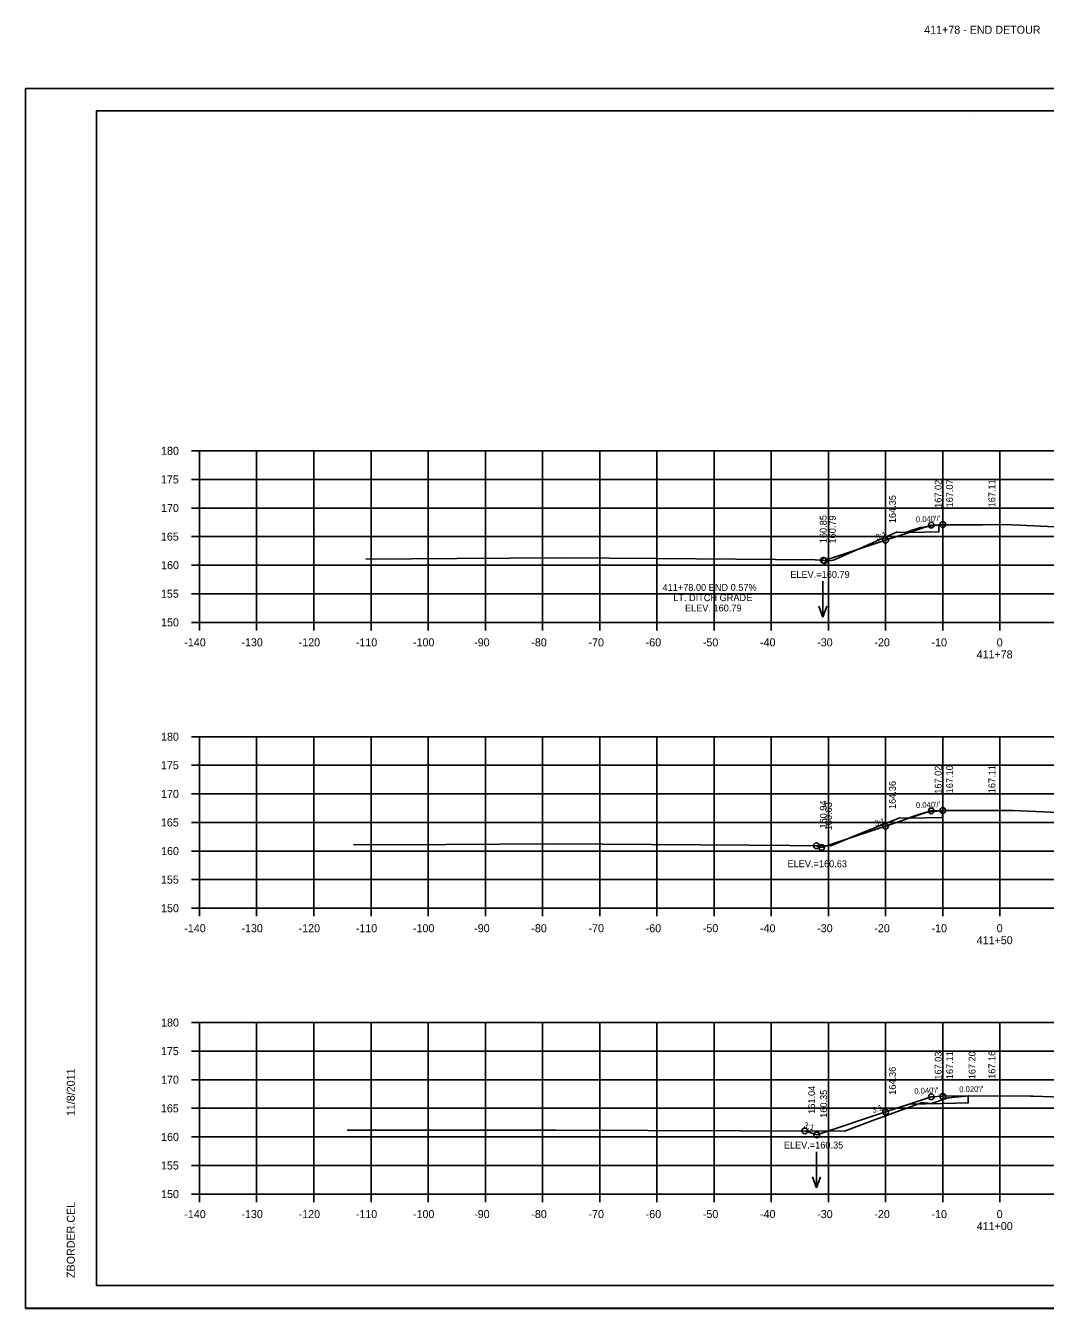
# Model space of a CAD drawing. Extents: x 1368503 to 1373085, y 379840 to 381833.
# Drawn here: x 1372751.7 to 1372930, y 381455 to 381679.3 of the extents above; entities that cross this region are included whole.
import ezdxf

# ---------------------------------------------------------------- set-up
doc = ezdxf.new("R2010")
doc.units = 0
for name, color, linetype in [('S_BRIDGE', 7, 'Continuous'), ('S_EDGE_PAVEMENT', 7, 'Continuous'), ('S_GRAVEL_ROAD', 7, 'Continuous'), ('S_MISC_BOUNDARY', 7, 'Continuous'), ('S_OBSCURES', 7, 'Continuous'), ('S_PHOTO_CENTERS', 7, 'Continuous'), ('S_PHOTO_NOTES', 7, 'Continuous'), ('S_RDW_PT_SYM', 7, 'Continuous'), ('S_SHOULDER', 7, 'Continuous'), ('S_STREAM_ANNOT', 7, 'Continuous'), ('S_TRAILS', 7, 'Continuous'), ('S_TRAILS_ANNOT', 7, 'Continuous'), ('S_TREE', 7, 'Continuous')]:
    doc.layers.add(name, color=color, linetype=linetype)

msp = doc.modelspace()

# ---------------------------------------------------------------- linework, layer by layer
at = {"layer": 'S_BRIDGE'}
for p, q in [((1372764.08, 381664.44), (1373080.26, 381664.44)), ((1372764.08, 381458.98), (1372764.08, 381664.44)), ((1372916.6, 381664.18), (1372916.6, 381664.18)), ((1372916.6, 381664.18), (1372916.6, 381664.18)), ((1372764.08, 381458.98), (1372764.08, 381458.98)), ((1373080.26, 381458.98), (1372764.08, 381458.98))]:
    msp.add_line(p, q, dxfattribs=at)
at = {"layer": 'S_EDGE_PAVEMENT'}
for p, q in [((1372780.68, 381604.98), (1372782.08, 381604.98)), ((1372782.08, 381574.98), (1372782.08, 381604.98)), ((1372780.68, 381599.98), (1372782.08, 381599.98)), ((1372780.68, 381594.98), (1372782.08, 381594.98)), ((1372780.68, 381589.98), (1372782.08, 381589.98)), ((1372780.68, 381584.98), (1372782.08, 381584.98)), ((1372780.68, 381579.98), (1372782.08, 381579.98)), ((1372780.68, 381574.98), (1372782.08, 381574.98)), ((1372782.08, 381574.98), (1373062.08, 381574.98)), ((1372782.08, 381573.58), (1372782.08, 381574.98)), ((1372792.08, 381573.58), (1372792.08, 381574.98)), ((1372802.08, 381573.58), (1372802.08, 381574.98)), ((1372812.08, 381573.58), (1372812.08, 381574.98)), ((1372822.08, 381573.58), (1372822.08, 381574.98)), ((1372832.08, 381573.58), (1372832.08, 381574.98)), ((1372842.08, 381573.58), (1372842.08, 381574.98)), ((1372852.08, 381573.58), (1372852.08, 381574.98)), ((1372862.08, 381573.58), (1372862.08, 381574.98)), ((1372872.08, 381573.58), (1372872.08, 381574.98)), ((1372882.08, 381573.58), (1372882.08, 381574.98)), ((1372892.08, 381573.58), (1372892.08, 381574.98)), ((1372902.08, 381573.58), (1372902.08, 381574.98)), ((1372912.08, 381573.58), (1372912.08, 381574.98)), ((1372922.08, 381573.58), (1372922.08, 381574.98)), ((1372780.68, 381554.98), (1372782.08, 381554.98)), ((1372782.08, 381524.98), (1372782.08, 381554.98)), ((1372780.68, 381549.98), (1372782.08, 381549.98)), ((1372780.68, 381544.98), (1372782.08, 381544.98)), ((1372780.68, 381539.98), (1372782.08, 381539.98)), ((1372780.68, 381534.98), (1372782.08, 381534.98)), ((1372780.68, 381529.98), (1372782.08, 381529.98)), ((1372780.68, 381524.98), (1372782.08, 381524.98)), ((1372782.08, 381524.98), (1373062.08, 381524.98)), ((1372782.08, 381523.58), (1372782.08, 381524.98)), ((1372792.08, 381523.58), (1372792.08, 381524.98)), ((1372802.08, 381523.58), (1372802.08, 381524.98)), ((1372812.08, 381523.58), (1372812.08, 381524.98)), ((1372822.08, 381523.58), (1372822.08, 381524.98)), ((1372832.08, 381523.58), (1372832.08, 381524.98)), ((1372842.08, 381523.58), (1372842.08, 381524.98)), ((1372852.08, 381523.58), (1372852.08, 381524.98)), ((1372862.08, 381523.58), (1372862.08, 381524.98)), ((1372872.08, 381523.58), (1372872.08, 381524.98)), ((1372882.08, 381523.58), (1372882.08, 381524.98)), ((1372892.08, 381523.58), (1372892.08, 381524.98)), ((1372902.08, 381523.58), (1372902.08, 381524.98)), ((1372912.08, 381523.58), (1372912.08, 381524.98)), ((1372922.08, 381523.58), (1372922.08, 381524.98)), ((1372780.68, 381504.98), (1372782.08, 381504.98)), ((1372782.08, 381474.98), (1372782.08, 381504.98)), ((1372780.68, 381499.98), (1372782.08, 381499.98)), ((1372780.68, 381494.98), (1372782.08, 381494.98)), ((1372780.68, 381489.98), (1372782.08, 381489.98)), ((1372780.68, 381484.98), (1372782.08, 381484.98)), ((1372780.68, 381479.98), (1372782.08, 381479.98)), ((1372780.68, 381474.98), (1372782.08, 381474.98)), ((1372782.08, 381474.98), (1373062.08, 381474.98)), ((1372782.08, 381473.58), (1372782.08, 381474.98)), ((1372792.08, 381473.58), (1372792.08, 381474.98)), ((1372802.08, 381473.58), (1372802.08, 381474.98)), ((1372812.08, 381473.58), (1372812.08, 381474.98)), ((1372822.08, 381473.58), (1372822.08, 381474.98)), ((1372832.08, 381473.58), (1372832.08, 381474.98)), ((1372842.08, 381473.58), (1372842.08, 381474.98)), ((1372852.08, 381473.58), (1372852.08, 381474.98)), ((1372862.08, 381473.58), (1372862.08, 381474.98)), ((1372872.08, 381473.58), (1372872.08, 381474.98)), ((1372882.08, 381473.58), (1372882.08, 381474.98)), ((1372892.08, 381473.58), (1372892.08, 381474.98)), ((1372902.08, 381473.58), (1372902.08, 381474.98)), ((1372912.08, 381473.58), (1372912.08, 381474.98)), ((1372922.08, 381473.58), (1372922.08, 381474.98))]:
    msp.add_line(p, q, dxfattribs=at)
at = {"layer": 'S_GRAVEL_ROAD'}
for p, q in [((1372891.13, 381582.16), (1372891.13, 381575.87)), ((1372891.13, 381575.87), (1372890.43, 381577.8)), ((1372891.13, 381575.87), (1372891.83, 381577.8)), ((1372889.99, 381482.35), (1372889.99, 381476.07)), ((1372889.99, 381476.07), (1372889.29, 381477.99)), ((1372889.99, 381476.07), (1372890.69, 381477.99))]:
    msp.add_line(p, q, dxfattribs=at)
at = {"layer": 'S_MISC_BOUNDARY'}
for points in [[(1372811.15, 381586.04), (1372827.09, 381586.13), (1372845.49, 381586.28), (1372861.99, 381586.16), (1372889.78, 381585.92), (1372892.15, 381585.76), (1372892.99, 381585.84), (1372903.49, 381590.53), (1372904.02, 381590.76), (1372904.1, 381590.75), (1372905.67, 381590.72), (1372906.41, 381591), (1372908.21, 381591.58), (1372909.31, 381591.71), (1372911.42, 381592.03), (1372919.01, 381592.06), (1372922.66, 381592.09), (1372925.58, 381591.97), (1372931.69, 381591.71)], [(1372809, 381536.08), (1372825.25, 381536.13), (1372844.04, 381536.23), (1372878.24, 381536.01), (1372892.52, 381535.89), (1372897.82, 381538.09), (1372904.59, 381540.8), (1372905.52, 381540.75), (1372906.02, 381540.75), (1372907.02, 381541.06), (1372909.03, 381541.7), (1372911.04, 381541.95), (1372912.05, 381542.08), (1372913.54, 381542.09), (1372923.31, 381542.09), (1372924.37, 381542.05), (1372932.34, 381541.73)], [(1372807.93, 381486.15), (1372817.95, 381486.16), (1372844.41, 381486.15), (1372876.71, 381486.06), (1372894.91, 381485.99), (1372899.7, 381487.79), (1372908.48, 381491.02), (1372909.87, 381490.81), (1372909.99, 381490.79), (1372910.12, 381490.83), (1372913.05, 381491.8), (1372916.12, 381492.13), (1372916.51, 381492.17), (1372916.54, 381492.17), (1372927.42, 381492.1), (1372927.92, 381492.09), (1372936.25, 381491.8)]]:
    msp.add_lwpolyline(points, dxfattribs=at)
at = {"layer": 'S_OBSCURES'}
for points in [[(1372911.42, 381592.05), (1372911.42, 381590.81), (1372906.22, 381590.71)], [(1372912.05, 381542.08), (1372912.05, 381540.83), (1372906.22, 381540.71)], [(1372916.54, 381492.17), (1372916.54, 381490.92), (1372912.08, 381490.83), (1372906.22, 381490.72)]]:
    msp.add_lwpolyline(points, dxfattribs=at)
at = {"layer": 'S_PHOTO_CENTERS'}
for p, q in [((1372782.08, 381604.98), (1373062.08, 381604.98)), ((1372782.08, 381574.98), (1372782.08, 381604.98)), ((1372792.08, 381574.98), (1372792.08, 381604.98)), ((1372802.08, 381574.98), (1372802.08, 381604.98)), ((1372812.08, 381574.98), (1372812.08, 381604.98)), ((1372822.08, 381574.98), (1372822.08, 381604.98)), ((1372832.08, 381574.98), (1372832.08, 381604.98)), ((1372842.08, 381574.98), (1372842.08, 381604.98)), ((1372852.08, 381574.98), (1372852.08, 381604.98)), ((1372862.08, 381574.98), (1372862.08, 381604.98)), ((1372872.08, 381574.98), (1372872.08, 381604.98)), ((1372882.08, 381574.98), (1372882.08, 381604.98)), ((1372892.08, 381574.98), (1372892.08, 381604.98)), ((1372902.08, 381574.98), (1372902.08, 381604.98)), ((1372912.08, 381574.98), (1372912.08, 381604.98)), ((1372922.08, 381574.98), (1372922.08, 381604.98)), ((1372782.08, 381599.98), (1373062.08, 381599.98)), ((1372782.08, 381594.98), (1373062.08, 381594.98)), ((1372782.08, 381589.98), (1373062.08, 381589.98)), ((1372782.08, 381584.98), (1373062.08, 381584.98)), ((1372782.08, 381579.98), (1373062.08, 381579.98)), ((1372782.08, 381574.98), (1373062.08, 381574.98)), ((1372782.08, 381554.98), (1373062.08, 381554.98)), ((1372782.08, 381524.98), (1372782.08, 381554.98)), ((1372792.08, 381524.98), (1372792.08, 381554.98)), ((1372802.08, 381524.98), (1372802.08, 381554.98)), ((1372812.08, 381524.98), (1372812.08, 381554.98)), ((1372822.08, 381524.98), (1372822.08, 381554.98)), ((1372832.08, 381524.98), (1372832.08, 381554.98)), ((1372842.08, 381524.98), (1372842.08, 381554.98)), ((1372852.08, 381524.98), (1372852.08, 381554.98)), ((1372862.08, 381524.98), (1372862.08, 381554.98)), ((1372872.08, 381524.98), (1372872.08, 381554.98)), ((1372882.08, 381524.98), (1372882.08, 381554.98)), ((1372892.08, 381524.98), (1372892.08, 381554.98)), ((1372902.08, 381524.98), (1372902.08, 381554.98)), ((1372912.08, 381524.98), (1372912.08, 381554.98)), ((1372922.08, 381524.98), (1372922.08, 381554.98)), ((1372782.08, 381549.98), (1373062.08, 381549.98)), ((1372782.08, 381544.98), (1373062.08, 381544.98)), ((1372782.08, 381539.98), (1373062.08, 381539.98)), ((1372782.08, 381534.98), (1373062.08, 381534.98)), ((1372782.08, 381529.98), (1373062.08, 381529.98)), ((1372782.08, 381524.98), (1373062.08, 381524.98)), ((1372782.08, 381504.98), (1373062.08, 381504.98)), ((1372782.08, 381474.98), (1372782.08, 381504.98)), ((1372792.08, 381474.98), (1372792.08, 381504.98)), ((1372802.08, 381474.98), (1372802.08, 381504.98)), ((1372812.08, 381474.98), (1372812.08, 381504.98)), ((1372822.08, 381474.98), (1372822.08, 381504.98)), ((1372832.08, 381474.98), (1372832.08, 381504.98)), ((1372842.08, 381474.98), (1372842.08, 381504.98)), ((1372852.08, 381474.98), (1372852.08, 381504.98)), ((1372862.08, 381474.98), (1372862.08, 381504.98)), ((1372872.08, 381474.98), (1372872.08, 381504.98)), ((1372882.08, 381474.98), (1372882.08, 381504.98)), ((1372892.08, 381474.98), (1372892.08, 381504.98)), ((1372902.08, 381474.98), (1372902.08, 381504.98)), ((1372912.08, 381474.98), (1372912.08, 381504.98)), ((1372922.08, 381474.98), (1372922.08, 381504.98)), ((1372782.08, 381499.98), (1373062.08, 381499.98)), ((1372782.08, 381494.98), (1373062.08, 381494.98)), ((1372782.08, 381489.98), (1373062.08, 381489.98)), ((1372782.08, 381484.98), (1373062.08, 381484.98)), ((1372782.08, 381479.98), (1373062.08, 381479.98)), ((1372782.08, 381474.98), (1373062.08, 381474.98))]:
    msp.add_line(p, q, dxfattribs=at)
at = {"layer": 'S_PHOTO_NOTES'}
for p, q in [((1372751.68, 381668.33), (1373085.01, 381668.33)), ((1372911.42, 381590.81), (1372911.42, 381592.05)), ((1372912.05, 381540.83), (1372912.05, 381542.08)), ((1372751.68, 381455), (1373085.01, 381455))]:
    msp.add_line(p, q, dxfattribs=at)
for points in [[(1372751.67, 381668.33), (1373085.01, 381668.33), (1373085.01, 381454.99), (1372751.67, 381454.99)], [(1372998, 381664.44), (1372998, 381654.56), (1373033.73, 381654.56), (1373033.73, 381651.64), (1373056.93, 381651.64), (1373056.93, 381627.3), (1373080.26, 381627.3), (1373080.26, 381458.98), (1372764.08, 381458.98), (1372764.08, 381664.44)]]:
    msp.add_lwpolyline(points, close=True, dxfattribs=at)
for centre in [(1372910.08, 381592), (1372912.08, 381592.08), (1372902.08, 381589.33), (1372891.21, 381585.83), (1372891.39, 381585.77), (1372910.08, 381542), (1372912.08, 381542.08), (1372902.08, 381539.33), (1372889.99, 381535.91), (1372890.9, 381535.61), (1372910.08, 381492), (1372912.08, 381492.08), (1372902.08, 381489.34), (1372887.96, 381486.02), (1372890.04, 381485.32)]:
    msp.add_circle(centre, 0.5, dxfattribs=at)
at = {"layer": 'S_STREAM_ANNOT'}
for points in [[(1372891.21, 381585.83), (1372891.39, 381585.77), (1372891.39, 381585.77), (1372902.08, 381589.33), (1372906.22, 381590.71), (1372906.22, 381590.71), (1372910.08, 381592), (1372911.42, 381592.05)], [(1372889.99, 381535.91), (1372890.9, 381535.61), (1372902.08, 381539.33), (1372906.22, 381540.71), (1372910.08, 381542), (1372912.05, 381542.08)], [(1372887.96, 381486.02), (1372890.04, 381485.32), (1372902.08, 381489.34), (1372906.22, 381490.72), (1372910.08, 381492), (1372912.08, 381492.08), (1372916.54, 381492.17)]]:
    msp.add_lwpolyline(points, dxfattribs=at)

# ---------------------------------------------------------------- texts
at = {"layer": 'S_BRIDGE'}
for s, p in [('11/8/2011', (1372760.27, 381488.62)), ('ZBORDER.CEL', (1372760.27, 381460.3))]:
    msp.add_text(s, height=1.4, rotation=90, dxfattribs=at).set_placement(p)
at = {"layer": 'S_GRAVEL_ROAD'}
for s, p in [('ELEV.=160.79', (1372885.41, 381582.76)), ('411+78.00 END 0.57%', (1372863.07, 381580.49)), ('LT. DITCH GRADE', (1372864.94, 381578.69)), ('ELEV. 160.79', (1372866.99, 381576.89)), ('ELEV.=160.63', (1372884.93, 381532.15)), ('ELEV.=160.35', (1372884.28, 381482.95))]:
    msp.add_text(s, height=1.2, dxfattribs=at).set_placement(p)
at = {"layer": 'S_RDW_PT_SYM'}
for s, rotation, p in [("0.040'/'", 2.2906, (1372907.41, 381592.49)), ('3:1', 18.434, (1372900.58, 381589.36)), ("0.040'/'", 2.2906, (1372907.41, 381542.49)), ('3:1', 18.4339, (1372900.33, 381539.28)), ("0.040'/'", 2.2906, (1372907.12, 381492.5)), ("0.020'/'", 1.1458, (1372914.97, 381492.79)), ('3:1', 18.4339, (1372899.9, 381489.14)), ('3:1', 341.5668, (1372887.67, 381486.67))]:
    msp.add_text(s, height=1, rotation=rotation, dxfattribs=at).set_placement(p)
at = {"layer": 'S_SHOULDER'}
for s, p in [('167.02', (1372911.88, 381595)), ('167.07', (1372913.88, 381595.08)), ('164.35', (1372903.88, 381592.33)), ('160.85', (1372891.77, 381588.83)), ('160.79', (1372893.38, 381588.77)), ('167.02', (1372911.88, 381545)), ('167.10', (1372913.88, 381545.08)), ('164.36', (1372903.88, 381542.33)), ('160.94', (1372891.79, 381538.91)), ('160.63', (1372892.7, 381538.61)), ('167.03', (1372911.88, 381495)), ('167.11', (1372913.88, 381495.08)), ('167.20', (1372917.81, 381495.06)), ('164.36', (1372903.88, 381492.34)), ('161.04', (1372889.76, 381489.02)), ('160.35', (1372891.84, 381488.32))]:
    msp.add_text(s, height=1.2, rotation=90, dxfattribs=at).set_placement(p)
at = {"layer": 'S_TRAILS'}
for s, p in [('180', (1372775.36, 381604.28)), ('175', (1372775.33, 381599.28)), ('170', (1372775.36, 381594.28)), ('165', (1372775.33, 381589.28)), ('160', (1372775.36, 381584.28)), ('155', (1372775.33, 381579.28)), ('150', (1372775.36, 381574.28)), ('-140', (1372779.42, 381570.78)), ('-130', (1372789.42, 381570.78)), ('-120', (1372799.42, 381570.78)), ('-110', (1372809.42, 381570.78)), ('-100', (1372819.42, 381570.78)), ('-90', (1372830.12, 381570.78)), ('-80', (1372840.12, 381570.78)), ('-70', (1372850.12, 381570.78)), ('-60', (1372860.12, 381570.78)), ('-50', (1372870.12, 381570.78)), ('-40', (1372880.12, 381570.78)), ('-30', (1372890.12, 381570.78)), ('-20', (1372900.12, 381570.78)), ('-10', (1372910.12, 381570.78)), ('0', (1372921.52, 381570.78)), ('411+78', (1372918, 381568.68)), ('180', (1372775.36, 381554.28)), ('175', (1372775.33, 381549.28)), ('170', (1372775.36, 381544.28)), ('165', (1372775.33, 381539.28)), ('160', (1372775.36, 381534.28)), ('155', (1372775.33, 381529.28)), ('150', (1372775.36, 381524.28)), ('-140', (1372779.42, 381520.78)), ('-130', (1372789.42, 381520.78)), ('-120', (1372799.42, 381520.78)), ('-110', (1372809.42, 381520.78)), ('-100', (1372819.42, 381520.78)), ('-90', (1372830.12, 381520.78)), ('-80', (1372840.12, 381520.78)), ('-70', (1372850.12, 381520.78)), ('-60', (1372860.12, 381520.78)), ('-50', (1372870.12, 381520.78)), ('-40', (1372880.12, 381520.78)), ('-30', (1372890.12, 381520.78)), ('-20', (1372900.12, 381520.78)), ('-10', (1372910.12, 381520.78)), ('0', (1372921.52, 381520.78)), ('411+50', (1372918.02, 381518.68)), ('180', (1372775.36, 381504.28)), ('175', (1372775.33, 381499.28)), ('170', (1372775.36, 381494.28)), ('165', (1372775.33, 381489.28)), ('160', (1372775.36, 381484.28)), ('155', (1372775.33, 381479.28)), ('150', (1372775.36, 381474.28)), ('-140', (1372779.42, 381470.78)), ('-130', (1372789.42, 381470.78)), ('-120', (1372799.42, 381470.78)), ('-110', (1372809.42, 381470.78)), ('-100', (1372819.42, 381470.78)), ('-90', (1372830.12, 381470.78)), ('-80', (1372840.12, 381470.78)), ('-70', (1372850.12, 381470.78)), ('-60', (1372860.12, 381470.78)), ('-50', (1372870.12, 381470.78)), ('-40', (1372880.12, 381470.78)), ('-30', (1372890.12, 381470.78)), ('-20', (1372900.12, 381470.78)), ('-10', (1372910.12, 381470.78)), ('0', (1372921.52, 381470.78)), ('411+00', (1372918.02, 381468.68))]:
    msp.add_text(s, height=1.4, dxfattribs=at).set_placement(p)
at = {"layer": 'S_TRAILS_ANNOT'}
for s, p in [('167.11', (1372921.28, 381595.09)), ('167.11', (1372921.28, 381545.09)), ('167.16', (1372921.28, 381495.13))]:
    msp.add_text(s, height=1.2, rotation=90, dxfattribs=at).set_placement(p)
at = {"layer": 'S_TREE'}
msp.add_text('411+78 - END DETOUR', height=1.4, dxfattribs=at).set_placement((1372908.84, 381677.93))

doc.saveas('drawing.dxf')
